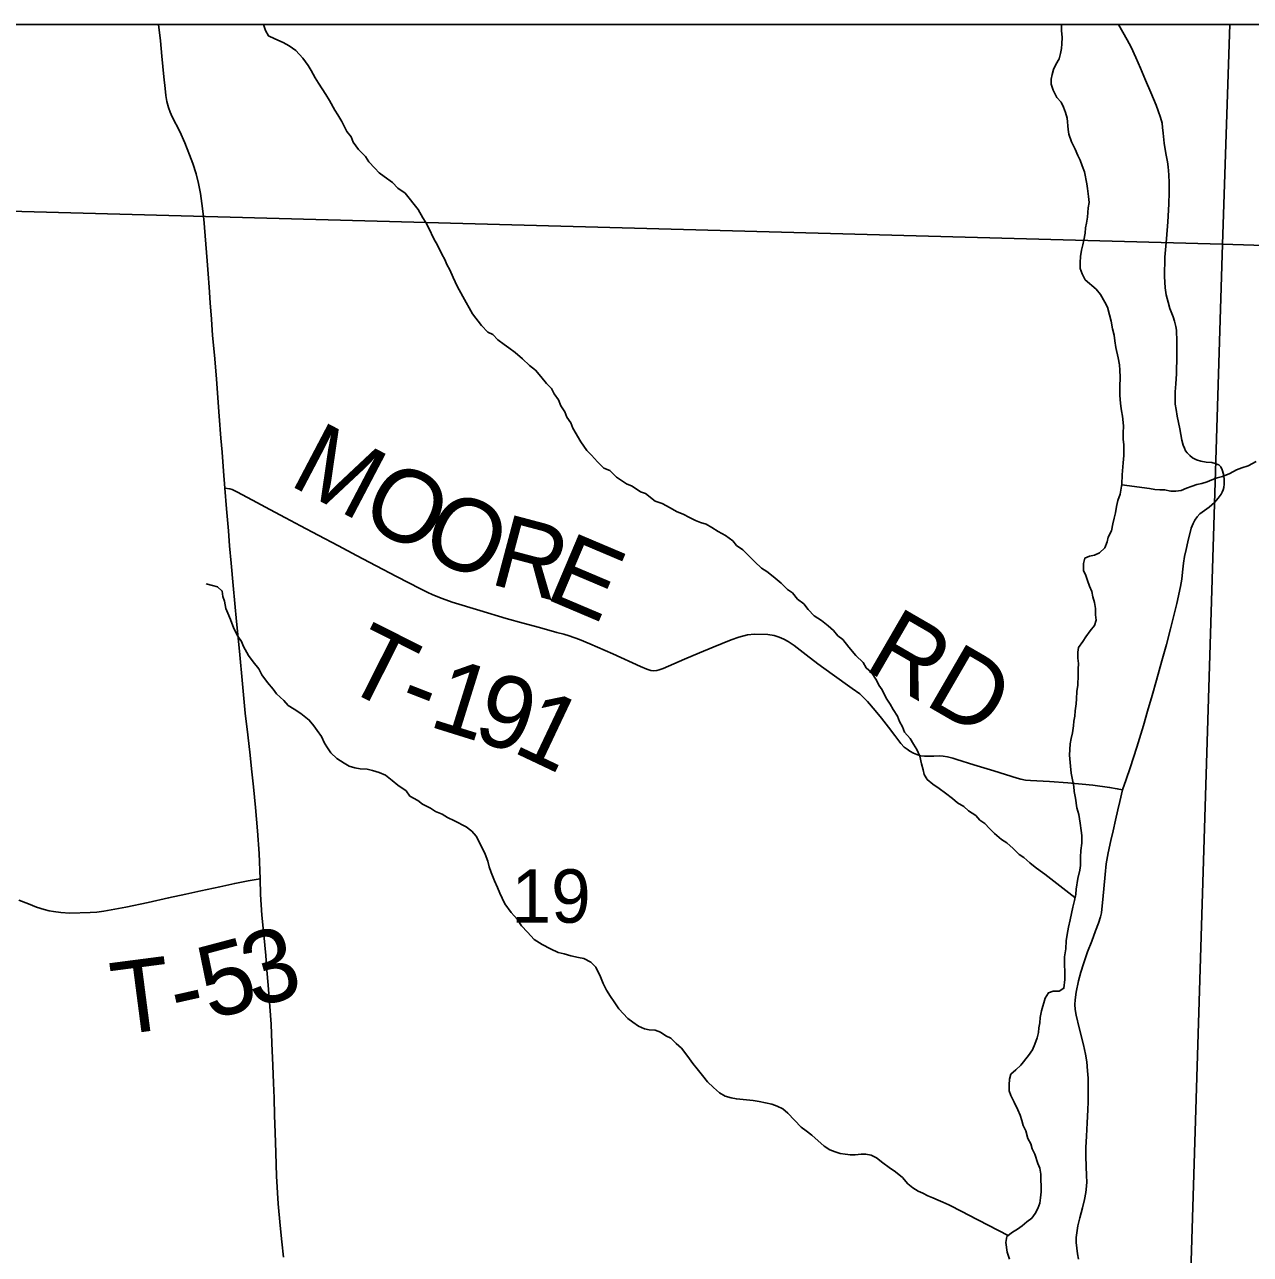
# Model space of a CAD drawing. Extents: x -3.3 to 34, y 0 to 56.8.
# Drawn here: x -2.17 to -1.209, y 33.913 to 34.877 of the extents above; entities that cross this region are included whole.
import ezdxf

# ---------------------------------------------------------------- set-up
doc = ezdxf.new("R2010")
doc.units = 0
for name, color, linetype in [('GM_X_Corporation', 7, 'Continuous'), ('GM_X_County_Road', 7, 'Continuous'), ('GM_X_Section_Text', 7, 'Continuous'), ('GM_X_Township_Road', 7, 'Continuous'), ('GM_X_Township_Road_Text', 7, 'Continuous'), ('GT_Project_Soil_Layers', 7, 'Continuous'), ('SH_Data', 7, 'Continuous')]:
    doc.layers.add(name, color=color, linetype=linetype)

msp = doc.modelspace()

# ---------------------------------------------------------------- linework, layer by layer
at = {"layer": 'GM_X_Corporation'}
for points in [[(1.84017, 34.87705), (-3.30393, 34.87705), (-3.30393, 33.7379), (-1.95594, 33.69761), (-1.4178, 33.68276), (-1.31578, 33.67985), (-1.26472, 33.67853), (-1.26192, 33.67846), (-1.25588, 33.6783), (-1.24768, 33.67809), (-0.68402, 33.66353), (0.07113, 33.6404), (0.53861, 33.62974), (1.16908, 33.60969), (1.26798, 33.60697), (1.38132, 33.6045), (1.39386, 33.60423), (1.40335, 33.60404), (1.51565, 33.60182), (1.54523, 33.60124), (1.79797, 33.59224), (1.81648, 34.17132), (1.8337, 34.72257), (1.83943, 34.85654)], [(-1.22534, 34.87705), (-2.24405, 34.87705), (-2.24907, 34.73274), (-1.23103, 34.70499)], [(-0.2111, 34.87705), (-1.22534, 34.87705), (-1.23103, 34.70499), (-0.21861, 34.67261)], [(-2.24907, 34.73274), (-1.23103, 34.70499), (-1.26284, 33.67933), (-2.28281, 33.7097)], [(-1.23103, 34.70499), (-0.21861, 34.67261), (-0.25432, 33.65409), (-1.26284, 33.67933)]]:
    msp.add_lwpolyline(points, close=True, dxfattribs=at)
at = {"layer": 'GM_X_County_Road'}
msp.add_lwpolyline([(-1.96699, 33.91128), (-1.96816, 33.92326), (-1.96942, 33.93605), (-1.97106, 33.95307), (-1.97229, 33.97461), (-1.9729, 33.99286), (-1.97343, 34.00897), (-1.97385, 34.0222), (-1.97426, 34.03601), (-1.9746, 34.04744), (-1.97522, 34.06149), (-1.97599, 34.07884), (-1.97665, 34.09388), (-1.97762, 34.10769), (-1.97879, 34.12446), (-1.97983, 34.13621), (-1.98084, 34.14756), (-1.98235, 34.16373), (-1.9838, 34.17929), (-1.98479, 34.19548), (-1.98528, 34.20773), (-1.98586, 34.22746), (-1.98718, 34.24538), (-1.98883, 34.26354), (-1.9903, 34.27966), (-1.99189, 34.29379), (-1.99309, 34.30448), (-1.99497, 34.32051), (-1.99696, 34.33753), (-1.99909, 34.36046), (-2.00147, 34.38619), (-2.0037, 34.40929), (-2.00501, 34.42335), (-2.00633, 34.43749), (-2.00791, 34.45507), (-2.00912, 34.46848), (-2.01012, 34.48037), (-2.01157, 34.49771), (-2.0129, 34.51377), (-2.01391, 34.52717), (-2.01503, 34.54189), (-2.01588, 34.55304), (-2.01719, 34.57032), (-2.01826, 34.58455), (-2.01939, 34.59951), (-2.02103, 34.61791), (-2.0224, 34.63331), (-2.02343, 34.64628), (-2.02436, 34.65912), (-2.02525, 34.67134), (-2.026, 34.6817), (-2.02674, 34.69188), (-2.0277, 34.70505), (-2.02942, 34.7247), (-2.03082, 34.73695), (-2.03181, 34.74459), (-2.03346, 34.75265), (-2.03526, 34.76013), (-2.03789, 34.7681), (-2.04052, 34.77509), (-2.04422, 34.7843), (-2.04817, 34.79326), (-2.05409, 34.80476), (-2.05581, 34.80838), (-2.05704, 34.81208), (-2.05828, 34.81676), (-2.05902, 34.82162), (-2.05968, 34.82704), (-2.06066, 34.83625), (-2.06222, 34.85229), (-2.06338, 34.8642), (-2.06483, 34.87705)], dxfattribs=at)
at = {"layer": 'GM_X_Township_Road'}
for points in [[(-1.30936, 34.27732), (-1.30653, 34.28546), (-1.30346, 34.29472), (-1.29832, 34.31096), (-1.29296, 34.32789), (-1.28981, 34.33904), (-1.28631, 34.35138), (-1.28295, 34.36324), (-1.27865, 34.37844), (-1.27502, 34.39122), (-1.27179, 34.40358), (-1.26691, 34.42351), (-1.26395, 34.43681), (-1.26307, 34.44249), (-1.26254, 34.44791), (-1.26181, 34.45514), (-1.26094, 34.46017), (-1.25969, 34.46572), (-1.25826, 34.47182), (-1.25556, 34.48239), (-1.25423, 34.48621), (-1.25288, 34.48874), (-1.25095, 34.49144), (-1.24879, 34.49363), (-1.24166, 34.49894), (-1.23735, 34.50258), (-1.23442, 34.50595), (-1.23224, 34.50907), (-1.2314, 34.51055), (-1.23065, 34.51242), (-1.22999, 34.51435), (-1.22972, 34.51685), (-1.22984, 34.52112), (-1.23041, 34.52489), (-1.23126, 34.52806), (-1.23239, 34.53044), (-1.2341, 34.53196), (-1.23683, 34.53313), (-1.23942, 34.53382), (-1.24402, 34.53421), (-1.24812, 34.53484), (-1.25146, 34.53589), (-1.25472, 34.53747), (-1.25684, 34.53932), (-1.25877, 34.54137), (-1.26, 34.54309), (-1.26099, 34.54523), (-1.26189, 34.54761), (-1.26288, 34.55148), (-1.26459, 34.56024), (-1.26653, 34.57016), (-1.26756, 34.57534), (-1.26809, 34.57974), (-1.26834, 34.58555), (-1.26824, 34.58916), (-1.2676, 34.59564), (-1.2672, 34.6034), (-1.26703, 34.61773), (-1.26692, 34.62862), (-1.2671, 34.63749), (-1.26764, 34.64045), (-1.26875, 34.64468), (-1.26982, 34.648), (-1.27227, 34.65449), (-1.27379, 34.65946), (-1.2752, 34.66534), (-1.27614, 34.67082), (-1.27662, 34.67975), (-1.27622, 34.69471), (-1.27502, 34.70922), (-1.27394, 34.72238), (-1.27323, 34.73626), (-1.27288, 34.74583), (-1.27281, 34.753), (-1.27308, 34.75934), (-1.27364, 34.76566), (-1.27416, 34.76944), (-1.2756, 34.77611), (-1.27693, 34.78419), (-1.27768, 34.792), (-1.27809, 34.79644), (-1.27851, 34.79991), (-1.27963, 34.80432), (-1.28143, 34.80938), (-1.2831, 34.81379), (-1.28728, 34.82373), (-1.29138, 34.83352), (-1.29527, 34.84281), (-1.29913, 34.85139), (-1.30273, 34.85938), (-1.30579, 34.86516), (-1.30911, 34.87109), (-1.31261, 34.87705)], [(-2.0129, 34.51377), (-2.00896, 34.51327), (-2.00707, 34.5127), (-2.00345, 34.51089), (-1.9913, 34.50442), (-1.97755, 34.49708), (-1.96538, 34.49059), (-1.95356, 34.48433), (-1.93972, 34.477), (-1.92379, 34.46856), (-1.90979, 34.46114), (-1.89429, 34.45293), (-1.87834, 34.44448), (-1.85955, 34.43486), (-1.85437, 34.43231), (-1.84985, 34.43025), (-1.84261, 34.42738), (-1.83472, 34.42458), (-1.81311, 34.41784), (-1.79231, 34.41167), (-1.77913, 34.40806), (-1.76629, 34.40453), (-1.75276, 34.40082), (-1.74734, 34.39943), (-1.74298, 34.39811), (-1.73501, 34.39515), (-1.72679, 34.39178), (-1.70887, 34.38397), (-1.68709, 34.37402), (-1.68215, 34.37197), (-1.67919, 34.37099), (-1.67704, 34.37071), (-1.6743, 34.37096), (-1.67255, 34.3714), (-1.66945, 34.37258), (-1.65259, 34.37985), (-1.6409, 34.38477), (-1.63024, 34.38926), (-1.61623, 34.3949), (-1.61007, 34.39696), (-1.60333, 34.39877), (-1.59781, 34.39951), (-1.58746, 34.39902), (-1.58253, 34.39828), (-1.5785, 34.39704), (-1.57497, 34.39556), (-1.57143, 34.39359), (-1.56666, 34.39055), (-1.55724, 34.38318), (-1.54817, 34.37608), (-1.53699, 34.36794), (-1.5212, 34.35692), (-1.5152, 34.35266), (-1.50929, 34.34657), (-1.50328, 34.33958), (-1.49843, 34.33367), (-1.49293, 34.32659), (-1.48777, 34.31987), (-1.48313, 34.31384), (-1.48047, 34.31092), (-1.47834, 34.30916), (-1.47602, 34.30759), (-1.47337, 34.30616), (-1.47058, 34.305), (-1.46767, 34.30413), (-1.46469, 34.30374), (-1.45729, 34.30388), (-1.45316, 34.30404), (-1.45002, 34.30383), (-1.44657, 34.30325), (-1.4423, 34.30214), (-1.43926, 34.30121), (-1.426, 34.29711), (-1.41043, 34.2923), (-1.39198, 34.28656), (-1.38919, 34.28582), (-1.3854, 34.28508), (-1.38163, 34.28475), (-1.36679, 34.28396), (-1.35236, 34.28294), (-1.3328, 34.28114), (-1.31964, 34.27933), (-1.31364, 34.27826), (-1.30936, 34.27732)], [(-1.34387, 33.9096), (-1.34475, 33.91384), (-1.34531, 33.91814), (-1.34573, 33.9226), (-1.34582, 33.92658), (-1.34539, 33.93031), (-1.34456, 33.93566), (-1.34304, 33.94209), (-1.34087, 33.94976), (-1.33932, 33.95632), (-1.33831, 33.96192), (-1.33769, 33.96672), (-1.33745, 33.97028), (-1.33759, 33.97504), (-1.33809, 33.9902), (-1.33817, 33.99711), (-1.33776, 34.00615), (-1.33719, 34.01649), (-1.33662, 34.02655), (-1.33633, 34.03294), (-1.3365, 34.05139), (-1.33678, 34.05711), (-1.33755, 34.06432), (-1.33848, 34.07037), (-1.34014, 34.07761), (-1.34344, 34.09094), (-1.34569, 34.10083), (-1.34651, 34.1054), (-1.34673, 34.10918), (-1.34653, 34.11296), (-1.34567, 34.11897), (-1.34389, 34.12769), (-1.34204, 34.13465), (-1.34015, 34.14118), (-1.33684, 34.15054), (-1.33364, 34.15881), (-1.33053, 34.16682), (-1.32828, 34.1728), (-1.32672, 34.17801), (-1.32601, 34.18099), (-1.32559, 34.18403), (-1.32506, 34.18877), (-1.32413, 34.19975), (-1.32317, 34.21112), (-1.32215, 34.21935), (-1.32063, 34.22806), (-1.31873, 34.23762), (-1.31692, 34.24533), (-1.31494, 34.25363), (-1.31302, 34.26163), (-1.3115, 34.26814), (-1.30936, 34.27732)], [(-2.17439, 34.19107), (-2.16666, 34.188), (-2.16035, 34.18559), (-2.15445, 34.18359), (-2.15046, 34.18259), (-2.14705, 34.18195), (-2.14132, 34.18126), (-2.13426, 34.18069), (-2.11831, 34.18118), (-2.11316, 34.18168), (-2.10767, 34.18243), (-2.09031, 34.18559), (-2.07304, 34.18915), (-2.05688, 34.19269), (-2.04346, 34.19563), (-2.03169, 34.19821), (-2.01678, 34.20147), (-2.0051, 34.20403), (-1.99457, 34.20617), (-1.98528, 34.20773)]]:
    msp.add_lwpolyline(points, dxfattribs=at)
at = {"layer": 'GT_Project_Soil_Layers'}
for points in [[(-1.98244, 34.87705), (-1.98093, 34.87237), (-1.97861, 34.86823), (-1.97365, 34.86602), (-1.96716, 34.86307), (-1.96257, 34.86048), (-1.95721, 34.85676), (-1.95183, 34.85076), (-1.94758, 34.84513), (-1.94525, 34.84099), (-1.94214, 34.83534), (-1.93943, 34.8312), (-1.93671, 34.82669), (-1.93362, 34.82217), (-1.93091, 34.81766), (-1.92663, 34.81013), (-1.92431, 34.80636), (-1.9212, 34.80109), (-1.9173, 34.79318), (-1.91384, 34.78905), (-1.91226, 34.7849), (-1.90802, 34.77927), (-1.90263, 34.77365), (-1.89992, 34.76951), (-1.89531, 34.76464), (-1.89184, 34.76089), (-1.88801, 34.75791), (-1.8815, 34.75345), (-1.87727, 34.74895), (-1.87153, 34.74486), (-1.8615, 34.73209), (-1.85762, 34.72569), (-1.85529, 34.72193), (-1.85296, 34.71741), (-1.84906, 34.70912), (-1.84633, 34.70422), (-1.84282, 34.69706), (-1.84049, 34.69292), (-1.83893, 34.68914), (-1.8366, 34.685), (-1.83386, 34.67896), (-1.83074, 34.67218), (-1.82645, 34.66389), (-1.81869, 34.65033), (-1.81174, 34.64132), (-1.80674, 34.63608), (-1.80292, 34.63423), (-1.79907, 34.63011), (-1.79409, 34.62639), (-1.79027, 34.62378), (-1.78529, 34.62006), (-1.77953, 34.6152), (-1.77416, 34.60996), (-1.76956, 34.60623), (-1.76532, 34.60136), (-1.76069, 34.59573), (-1.75685, 34.59199), (-1.7549, 34.58784), (-1.75142, 34.58295), (-1.74946, 34.57842), (-1.74636, 34.57354), (-1.74479, 34.56938), (-1.74169, 34.56487), (-1.74012, 34.56072), (-1.73391, 34.55018), (-1.72927, 34.54341), (-1.72543, 34.53967), (-1.72081, 34.53442), (-1.71581, 34.52955), (-1.71124, 34.52772), (-1.70586, 34.52248), (-1.6982, 34.51727), (-1.69363, 34.51544), (-1.68712, 34.51098), (-1.68331, 34.50951), (-1.67565, 34.50354)], [(-1.35734, 34.87705), (-1.35723, 34.87611), (-1.35718, 34.87232), (-1.35673, 34.86701), (-1.35704, 34.86207), (-1.35737, 34.85828), (-1.35808, 34.85447), (-1.35916, 34.85028), (-1.36175, 34.84569), (-1.36359, 34.84187), (-1.36468, 34.83806), (-1.36539, 34.83425), (-1.36534, 34.83046), (-1.36375, 34.82555), (-1.36102, 34.81989), (-1.35756, 34.81615), (-1.35561, 34.81238), (-1.35404, 34.80823), (-1.35284, 34.80369), (-1.35197, 34.79498), (-1.35154, 34.79119), (-1.34956, 34.78514), (-1.34645, 34.77949), (-1.34449, 34.77459), (-1.34254, 34.77082), (-1.34096, 34.76629), (-1.33938, 34.76176), (-1.33736, 34.7523), (-1.33693, 34.74851), (-1.33609, 34.74245), (-1.33564, 34.73752), (-1.33635, 34.73334), (-1.33701, 34.72611), (-1.3377, 34.72155), (-1.33841, 34.71775), (-1.33874, 34.71357), (-1.3398, 34.70824), (-1.34051, 34.70443), (-1.34159, 34.70024), (-1.34228, 34.6953), (-1.3426, 34.69074), (-1.34253, 34.68581), (-1.34096, 34.68166), (-1.33862, 34.67713), (-1.33018, 34.66966), (-1.32671, 34.66554), (-1.32322, 34.65951), (-1.32127, 34.65575), (-1.31967, 34.6497), (-1.31847, 34.64478), (-1.31725, 34.63872), (-1.31604, 34.63381), (-1.3156, 34.62926), (-1.31477, 34.62396), (-1.31277, 34.61601), (-1.31194, 34.61033), (-1.3115, 34.60617), (-1.31143, 34.60085), (-1.3117, 34.59326), (-1.31162, 34.58681), (-1.31119, 34.58302), (-1.31074, 34.57809), (-1.31031, 34.5743), (-1.3095, 34.57014), (-1.30863, 34.56256), (-1.30894, 34.55686), (-1.30887, 34.55193), (-1.30844, 34.54814), (-1.30837, 34.54321), (-1.30832, 34.53941), (-1.309, 34.53371), (-1.30963, 34.52421), (-1.30992, 34.517), (-1.31132, 34.509), (-1.31315, 34.50404), (-1.31423, 34.49947), (-1.31492, 34.49453), (-1.316, 34.49034), (-1.31708, 34.48577), (-1.31814, 34.48044), (-1.32073, 34.47547), (-1.32144, 34.47167), (-1.32327, 34.46709), (-1.32739, 34.46323)], [(-1.20474, 34.53479), (-1.21114, 34.53129), (-1.21605, 34.5297), (-1.2202, 34.52812), (-1.22547, 34.52539), (-1.23113, 34.52304), (-1.23528, 34.52184), (-1.23943, 34.52026), (-1.2432, 34.51869), (-1.24736, 34.51749), (-1.25114, 34.51668), (-1.25491, 34.51549), (-1.25944, 34.51391), (-1.26359, 34.51195), (-1.26775, 34.51151), (-1.27154, 34.51146), (-1.27649, 34.51253), (-1.28028, 34.51248), (-1.28407, 34.5128), (-1.28825, 34.5135), (-1.31003, 34.51637)], [(-1.67565, 34.50354), (-1.67031, 34.50172), (-1.66382, 34.49839), (-1.65885, 34.49543), (-1.65313, 34.49323), (-1.64931, 34.491), (-1.64397, 34.48842), (-1.64016, 34.48696), (-1.63559, 34.4855), (-1.63138, 34.4829), (-1.62641, 34.47994), (-1.62068, 34.4766), (-1.61494, 34.47251), (-1.61185, 34.46875), (-1.60688, 34.46541), (-1.60264, 34.46091), (-1.59765, 34.45605), (-1.59227, 34.45119), (-1.58807, 34.44859), (-1.58308, 34.44448), (-1.57695, 34.43925), (-1.57195, 34.43439), (-1.56813, 34.43179), (-1.56427, 34.42691), (-1.55929, 34.42318), (-1.55581, 34.41867), (-1.5512, 34.4138), (-1.54546, 34.41009), (-1.54009, 34.40599), (-1.53587, 34.40225), (-1.53241, 34.39812), (-1.52857, 34.39514), (-1.52394, 34.38913), (-1.51855, 34.38275), (-1.51278, 34.37714), (-1.51045, 34.373), (-1.50623, 34.36926), (-1.50236, 34.36324), (-1.50041, 34.35947), (-1.4977, 34.35572), (-1.49458, 34.34931), (-1.49148, 34.34442), (-1.48915, 34.34027), (-1.48567, 34.33501), (-1.4841, 34.33085), (-1.48177, 34.32671), (-1.48019, 34.32256), (-1.47595, 34.31768), (-1.47324, 34.31317), (-1.47053, 34.30903), (-1.46818, 34.30375), (-1.46696, 34.29769), (-1.46576, 34.29315), (-1.46495, 34.28937), (-1.46263, 34.2856), (-1.45803, 34.28187), (-1.45305, 34.27853), (-1.44807, 34.2748), (-1.44271, 34.2707), (-1.43887, 34.26734), (-1.4339, 34.26437), (-1.43006, 34.26101), (-1.42432, 34.25729), (-1.42124, 34.25354), (-1.41741, 34.25093), (-1.41357, 34.24719), (-1.40972, 34.24307), (-1.40435, 34.23859), (-1.40015, 34.23599), (-1.39516, 34.23151), (-1.39054, 34.22664), (-1.38672, 34.22441), (-1.38211, 34.2203), (-1.3779, 34.21694), (-1.37406, 34.21396), (-1.37024, 34.21135), (-1.34674, 34.19296)], [(-1.32739, 34.46323), (-1.33153, 34.46128), (-1.33531, 34.46046), (-1.33909, 34.45889), (-1.34017, 34.45471), (-1.34009, 34.44939), (-1.33814, 34.44524), (-1.33695, 34.44146), (-1.33538, 34.43693), (-1.33342, 34.43278), (-1.33261, 34.42862), (-1.33141, 34.42408), (-1.33059, 34.41954), (-1.33052, 34.41461), (-1.33009, 34.41044), (-1.33155, 34.40624), (-1.3349, 34.40202), (-1.33825, 34.39742), (-1.34048, 34.39359), (-1.34383, 34.38899), (-1.34453, 34.38518), (-1.34447, 34.38063), (-1.34403, 34.37646), (-1.34435, 34.3719), (-1.34429, 34.36735), (-1.34456, 34.35937), (-1.34526, 34.35443), (-1.34556, 34.34873), (-1.34588, 34.34493), (-1.34657, 34.33923), (-1.34689, 34.33505), (-1.34759, 34.33124), (-1.34792, 34.32744), (-1.34861, 34.32212), (-1.34969, 34.31755), (-1.35038, 34.31336), (-1.35102, 34.30462), (-1.35015, 34.29591), (-1.3497, 34.2906), (-1.34766, 34.28), (-1.34723, 34.27621), (-1.3464, 34.2709), (-1.34516, 34.26333), (-1.34357, 34.25804), (-1.34272, 34.25122), (-1.34188, 34.24553), (-1.34145, 34.24175), (-1.34137, 34.23567), (-1.34205, 34.22997), (-1.34236, 34.22465), (-1.34227, 34.2182), (-1.34298, 34.21439), (-1.34441, 34.20792), (-1.34581, 34.19955), (-1.34614, 34.19575), (-1.34721, 34.1908), (-1.34827, 34.18547), (-1.35042, 34.17557), (-1.35185, 34.16985), (-1.35291, 34.16415), (-1.3536, 34.1592), (-1.35389, 34.15275), (-1.35495, 34.14665), (-1.35471, 34.12882), (-1.35537, 34.12197), (-1.35913, 34.11964), (-1.36368, 34.11958), (-1.36746, 34.11839), (-1.37006, 34.11418), (-1.37295, 34.10427), (-1.37402, 34.09894), (-1.37434, 34.09476), (-1.37505, 34.09095), (-1.37538, 34.08715), (-1.37646, 34.08296), (-1.37828, 34.078), (-1.38012, 34.0738), (-1.38309, 34.0692), (-1.38906, 34.06153), (-1.39318, 34.05805), (-1.39693, 34.05458), (-1.39801, 34.05077), (-1.39833, 34.04621), (-1.39827, 34.04165), (-1.39708, 34.03788), (-1.39435, 34.0326), (-1.39162, 34.02656), (-1.38966, 34.02241), (-1.38847, 34.01825), (-1.38728, 34.01447), (-1.38533, 34.01032), (-1.38373, 34.00427), (-1.3814, 34.00013), (-1.3802, 33.99597), (-1.37825, 33.99182), (-1.37588, 33.98464), (-1.37431, 33.98087), (-1.37349, 33.97632), (-1.3733, 33.96228), (-1.37362, 33.95772), (-1.37432, 33.95353)], [(-2.02742, 34.43872), (-2.02247, 34.43765), (-2.01867, 34.43657), (-2.01483, 34.4332), (-2.01439, 34.42903), (-2.0132, 34.42525), (-2.01199, 34.41958), (-2.01042, 34.4158), (-2.00846, 34.4109), (-2.00571, 34.40373), (-2.00259, 34.3977), (-1.99988, 34.39356), (-1.99831, 34.38978), (-1.99443, 34.38263), (-1.99057, 34.37775), (-1.98632, 34.37211), (-1.98399, 34.36759), (-1.97935, 34.36158), (-1.97511, 34.35632), (-1.97241, 34.35256), (-1.96665, 34.34733), (-1.96318, 34.34358), (-1.95859, 34.34061), (-1.95324, 34.33727), (-1.94672, 34.33204), (-1.94325, 34.32754), (-1.94054, 34.32378), (-1.93707, 34.31927), (-1.93472, 34.31399), (-1.9324, 34.31023), (-1.92969, 34.30647), (-1.92508, 34.30198), (-1.91934, 34.29826), (-1.91552, 34.29603), (-1.91095, 34.29458), (-1.90677, 34.29388), (-1.90146, 34.29357), (-1.89727, 34.29249), (-1.89194, 34.29105), (-1.88699, 34.28884), (-1.88162, 34.28474), (-1.8774, 34.281), (-1.87089, 34.27653), (-1.8678, 34.2724), (-1.86169, 34.26907), (-1.85786, 34.26609), (-1.85175, 34.26313), (-1.84792, 34.26053), (-1.84258, 34.25832), (-1.83838, 34.25572), (-1.83303, 34.25314), (-1.82387, 34.24833), (-1.81927, 34.24498), (-1.81581, 34.24123), (-1.81347, 34.23671), (-1.80879, 34.22691), (-1.80682, 34.22162), (-1.80562, 34.21708), (-1.80405, 34.21255), (-1.80168, 34.20613), (-1.79934, 34.20085), (-1.79738, 34.19632), (-1.79543, 34.19255), (-1.79347, 34.18802), (-1.78845, 34.18126), (-1.78383, 34.17601), (-1.78035, 34.17074), (-1.77573, 34.16587), (-1.77035, 34.16025), (-1.76422, 34.15616), (-1.75773, 34.15283), (-1.75163, 34.14988), (-1.74706, 34.1488), (-1.74173, 34.14736), (-1.73565, 34.14592), (-1.73146, 34.14522), (-1.72612, 34.14226), (-1.72227, 34.13852), (-1.71838, 34.13098), (-1.71641, 34.12569), (-1.71368, 34.12042), (-1.71058, 34.11552), (-1.70787, 34.11139), (-1.70401, 34.10575), (-1.69708, 34.09825), (-1.69325, 34.09526), (-1.68866, 34.09229), (-1.68408, 34.09008), (-1.68027, 34.08937), (-1.67572, 34.08905), (-1.67153, 34.08759), (-1.66732, 34.08461), (-1.6635, 34.08277), (-1.65927, 34.07865), (-1.65505, 34.07491), (-1.65003, 34.06853), (-1.64617, 34.06289), (-1.6427, 34.05876), (-1.63845, 34.0535), (-1.63459, 34.04862), (-1.62999, 34.04413)], [(-1.62999, 34.04413), (-1.62538, 34.04002), (-1.62079, 34.03742), (-1.61622, 34.03597), (-1.61204, 34.03527), (-1.60407, 34.03462), (-1.59875, 34.03393), (-1.59419, 34.03324), (-1.58431, 34.0311), (-1.58011, 34.02964), (-1.57553, 34.02742), (-1.5717, 34.02406), (-1.56131, 34.01319), (-1.55748, 34.01021), (-1.55288, 34.00686), (-1.54329, 33.99826), (-1.5387, 33.99528), (-1.5345, 33.99382), (-1.53069, 33.99236), (-1.5269, 33.99203), (-1.52272, 33.99133), (-1.51892, 33.99138), (-1.51438, 33.99183), (-1.51059, 33.99188), (-1.50641, 33.99118), (-1.50221, 33.98896), (-1.49723, 33.98523), (-1.49225, 33.9815), (-1.48727, 33.97816), (-1.4819, 33.97367), (-1.47766, 33.9688), (-1.47383, 33.96543), (-1.46962, 33.96284), (-1.46581, 33.96137), (-1.46199, 33.95914), (-1.45817, 33.95768), (-1.45398, 33.95584), (-1.45017, 33.95437), (-1.44559, 33.95216), (-1.43489, 33.94661), (-1.43031, 33.9444), (-1.39916, 33.9281)], [(-1.37432, 33.95353), (-1.37578, 33.94933), (-1.378, 33.94551), (-1.3806, 33.94167), (-1.38436, 33.93896), (-1.38811, 33.93587), (-1.39186, 33.93316), (-1.39562, 33.93083), (-1.40012, 33.92735), (-1.40082, 33.92279), (-1.39996, 33.91521), (-1.39799, 33.90954)]]:
    msp.add_lwpolyline(points, dxfattribs=at)
at = {"layer": 'SH_Data'}
msp.add_line((-3.30393, 34.87705), (3.49607, 34.87705), dxfattribs=at)

# ---------------------------------------------------------------- texts
at = {"layer": 'GM_X_Section_Text'}
msp.add_text('19', height=0.041856, rotation=0.00001, dxfattribs=at).set_placement((-1.78839, 34.17327))
at = {"layer": 'GM_X_Township_Road_Text'}
for s, height, rotation, p in [('M', 0.05682, 332.29098, (-1.96378, 34.51692)), ('O', 0.05682, 332.35936, (-1.90912, 34.48821)), ('O', 0.05682, 335.31622, (-1.86195, 34.4636)), ('R', 0.05682, 345.13973, (-1.80652, 34.43913)), ('E', 0.05682, 337.03101, (-1.76342, 34.42785)), ('RD', 0.056818, 329.88741, (-1.51344, 34.37254)), ('T', 0.05682, 333.21837, (-1.92341, 34.35902)), ('1', 0.05682, 342.67349, (-1.85426, 34.32759)), ('9', 0.05682, 343.33189, (-1.82016, 34.31696)), ('-', 0.05682, 338.79385, (-1.87997, 34.33742)), ('1', 0.05682, 334.6662, (-1.78875, 34.30774)), ('3', 0.05682, 15.77648, (-1.99011, 34.10635)), ('5', 0.05682, 14.85226, (-2.0249, 34.09712)), ('T', 0.05682, 7.40887, (-2.09771, 34.08499)), ('-', 0.05682, 12.62304, (-2.05002, 34.09145))]:
    msp.add_text(s, height=height, rotation=rotation, dxfattribs=at).set_placement(p)

doc.saveas('drawing.dxf')
